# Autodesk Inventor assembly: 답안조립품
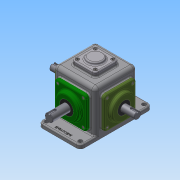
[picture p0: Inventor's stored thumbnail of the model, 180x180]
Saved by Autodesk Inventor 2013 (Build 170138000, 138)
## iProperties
Created: 2018-09
Part Number: 답안조립품
Document SubType Name: Assembly
Designer: Administrator
Author: Administrator
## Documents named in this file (15)
- C:\Users\Administrator\Desktop\380908V1007\답안조립품.iam
- C:\Users\Administrator\Desktop\380908V1007\본체.ipt
- C:\Users\Administrator\Desktop\380908V1007\서브축.ipt
- C:\Users\Administrator\Desktop\380908V1007\메인베벨기어.ipt
- C:\Users\Administrator\Desktop\380908V1007\메인축.ipt
- C:\Users\Administrator\Desktop\380908V1007\키 4x4.ipt
- C:\Users\Administrator\Desktop\380908V1007\베어링 6204.ipt
- C:\Users\Administrator\Desktop\380908V1007\메인커버.ipt
- C:\Users\Administrator\Desktop\380908V1007\오일 실 20 35 8.ipt
- C:\Users\Administrator\Desktop\380908V1007\볼트 M4.ipt
- C:\Users\Administrator\Desktop\380908V1007\서브베벨기어.ipt
- C:\Users\Administrator\Desktop\380908V1007\베어링 6203.ipt
- C:\Users\Administrator\Desktop\380908V1007\서브커버.ipt
- C:\Users\Administrator\Desktop\380908V1007\오일 실 17 32 8.ipt
- C:\Users\Administrator\Desktop\380908V1007\상부커버.ipt
